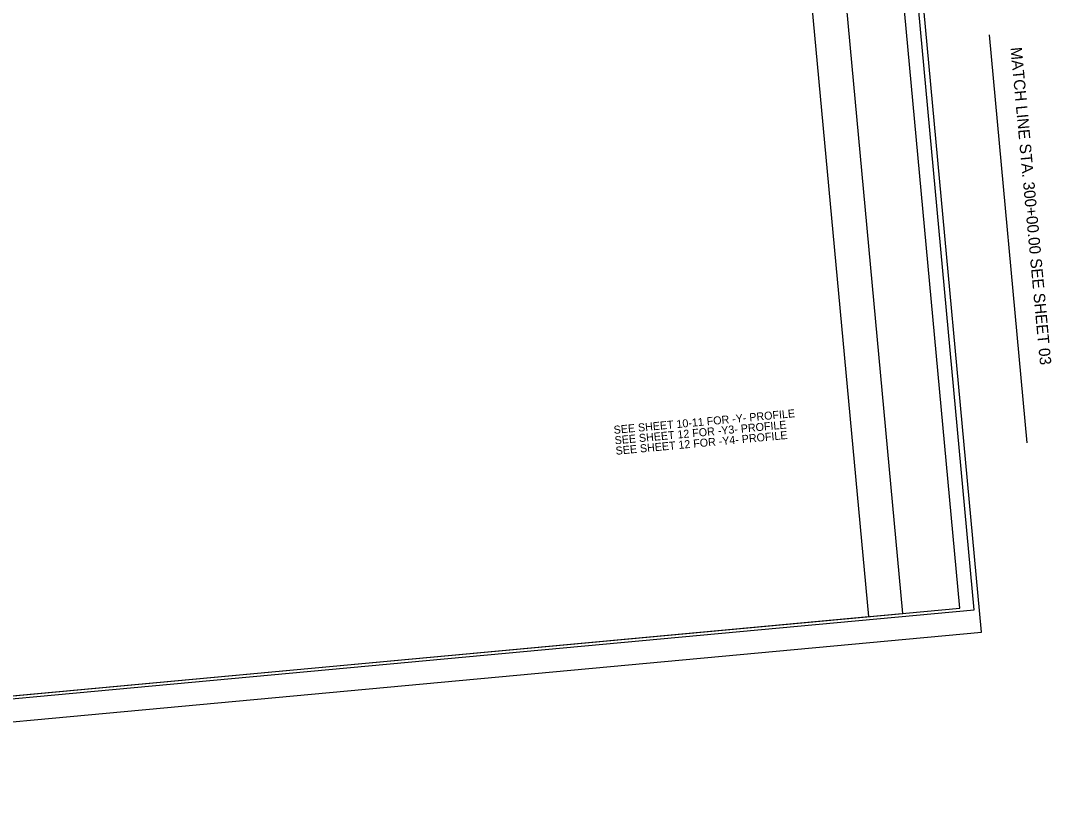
# Model space of a CAD drawing. Extents: x 1724152 to 1726026, y 971581 to 972827.
# Drawn here: x 1725089 to 1725990, y 971581 to 972271 of the extents above; entities that cross this region are included whole.
import ezdxf

# ---------------------------------------------------------------- set-up
doc = ezdxf.new("R2010")
doc.units = 0
for name, color, linetype in [('Matchline', 7, 'Continuous'), ('Matchline Text', 7, 'Continuous'), ('Prop Dimension', 7, 'Continuous'), ('Sheet Clip Boundary CELL', 7, 'Continuous'), ('Sheet Layout Plan Border', 7, 'Continuous'), ('Sheet Plan CELL', 7, 'Continuous'), ('Sheet Plot Border Inside CELL', 7, 'Continuous'), ('Sheet Plot Border Outside CELL', 7, 'Continuous')]:
    doc.layers.add(name, color=color, linetype=linetype)

msp = doc.modelspace()

# ---------------------------------------------------------------- linework, layer by layer
at = {"layer": 'Matchline'}
msp.add_line((1725936, 972258.49), (1725969, 971901.86), dxfattribs=at)
at = {"layer": 'Sheet Clip Boundary CELL'}
msp.add_lwpolyline([(1724466.5, 971623.53), (1725860.56, 971752.51), (1725783.31, 972587.46), (1725594.85, 972570.02), (1725575.37, 972780.61), (1724369.77, 972669.06)], close=True, dxfattribs=at)
at = {"layer": 'Sheet Layout Plan Border'}
msp.add_lwpolyline([(1725733.83, 972795.27), (1725723.88, 972794.35), (1724369.77, 972669.06), (1724487.01, 971625.42), (1724638.15, 971639.41), (1724679.57, 971643.24), (1725830.66, 971749.75)], close=True, dxfattribs=at)
at = {"layer": 'Sheet Plan CELL'}
msp.add_lwpolyline([(1725813.64, 972802.65), (1724319.98, 972664.46), (1724416.72, 971618.92), (1725910.35, 971757.12)], close=True, dxfattribs=at)
at = {"layer": 'Sheet Plot Border Inside CELL'}
msp.add_lwpolyline([(1724264.11, 971602.28), (1725923.01, 971755.78), (1725825.83, 972806.28), (1724166.92, 972652.79)], close=True, dxfattribs=at)
at = {"layer": 'Sheet Plot Border Outside CELL'}
msp.add_lwpolyline([(1724253.01, 971581.17), (1725929.35, 971736.27), (1725828.47, 972826.61), (1724152.13, 972671.51)], close=True, dxfattribs=at)

# ---------------------------------------------------------------- texts
at = {"layer": 'Matchline Text'}
msp.add_text('MATCH LINE STA. 300+00.00 SEE SHEET 03', height=10, rotation=275.33529, dxfattribs=at).set_placement((1725954.62, 972247.28))
at = {"layer": 'Prop Dimension'}
for s, p in [('SEE SHEET 10-11 FOR -Y- PROFILE', (1725607.96, 971909.51)), ('SEE SHEET 12 FOR -Y3- PROFILE', (1725608.8, 971900.38)), ('SEE SHEET 12 FOR -Y4- PROFILE', (1725609.65, 971891.24))]:
    msp.add_text(s, height=7, rotation=5.28619, dxfattribs=at).set_placement(p)

doc.saveas('drawing.dxf')
